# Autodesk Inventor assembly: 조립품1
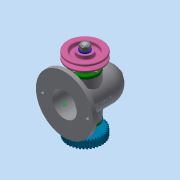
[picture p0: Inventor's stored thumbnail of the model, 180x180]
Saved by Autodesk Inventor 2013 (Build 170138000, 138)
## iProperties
Created: 2019-11
Part Number: 조립품1
Document SubType Name: Assembly
Designer: Administrator
Author: Administrator
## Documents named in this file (15)
- C:\Users\Administrator\Desktop\491104v1025\조립품1.iam
- C:\Users\Administrator\Desktop\491104v1025\본체.ipt
- C:\Users\Administrator\Desktop\491104v1025\V-벨트풀리.ipt
- V-벨트풀리.ipt
- C:\Users\Administrator\Desktop\491104v1025\베어링 6203.ipt
- C:\Users\Administrator\Desktop\491104v1025\볼트 M4.ipt
- C:\Users\Administrator\Desktop\491104v1025\부시.ipt
- C:\Users\Administrator\Desktop\491104v1025\스퍼기어.ipt
- C:\Users\Administrator\Desktop\491104v1025\와셔 12x24.ipt
- C:\Users\Administrator\Desktop\491104v1025\축.ipt
- C:\Users\Administrator\Desktop\491104v1025\키 5x5x12.ipt
- C:\Users\Administrator\Desktop\491104v1025\너트 M12x1.25.ipt
- C:\Users\Administrator\Desktop\491104v1025\커버.ipt
- C:\Users\Administrator\Desktop\491104v1025\커버_MIR.ipt
- C:\Users\Administrator\Desktop\491104v1025\오일 실 26 38 8.ipt
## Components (1 placed, 1 different names)
1. V-벨트풀리:1
